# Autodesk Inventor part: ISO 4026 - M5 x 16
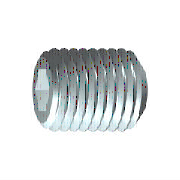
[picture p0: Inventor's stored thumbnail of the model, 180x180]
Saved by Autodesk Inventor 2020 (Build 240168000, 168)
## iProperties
IsCustomPart: 0
Created: 2010-01
Part Number: ISO 4026 - M5 x 16
Material: Stainless Steel, 440C
Description: Hexagon socket set screws with flat point
Document SubType Name: Modeling
Standard: ISO 4026
Designer: sauflet
Standard Revision: Third edition 2003-12-01
Standards Organization: ISO
Language: en-US
Size Designation: M5 x 16
Categories: <MemberInstance><Categories><Category DisplayName="Fasteners" InternalName="e4da775c-781d-43d5-af7c-5136215cf5a6" Mnemonic="FSTN"><Category DisplayName="Bolts"
Density: 7.75 g/cm^3
Appearance: Steel
Author: sauflet
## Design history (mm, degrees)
sketch "Sketch1"
  geometry: L1 (0, 0)-(12.167, 0); L2 (16, 1.443)-(16, 2.5); L3 (16, 2.5)-(0, 2.5); L4 (16, 1.443)-(13, 1.443); L5 (13, 1.443)-(12.167, 0); L6 (0, -0.5)-(0, 3) reference; L7 (0, 2.5)-(0, 0)
  constraints: 13 end point, 3 parallel, 1 collinear, 1 perpendicular, 1 point on line
  dimensions: "d0" = 3 distance of L2.start L4.end (= INTI); "d1" = 60 deg angle of L5 L1; "d2" = 5 diameter of L3 L1 (= NND); "d3" = 2.88675 diameter of L4 L1 (= 1.1547 x SW); "d5" = 16 distance from line of L2 L3.end (= NLG)
revolve "Body" sketch "Sketch1" stored, may be unused: angle "d6" = 90 deg
sketch "Sketch2"
  geometry: L1 (-0.722, 1.25)-(0.722, 1.25); L2 (0.722, 1.25)-(1.443, 0); L3 (1.443, 0)-(0.722, -1.25); L4 (0.722, -1.25)-(-0.722, -1.25); L5 (-0.722, -1.25)-(-1.443, 0); L6 (-1.443, 0)-(-0.722, 1.25); A1 r 1.443 centre (0, 0) between (-0.722, 1.25) and (0.722, 1.25) reference; 2 further points
  constraints: 12 end point, 2 point on circle, 1 coincident, 1 horizontal, 11 other
extrude "Slot" join sketch "Sketch2" taper "d9" = 0 deg; stored distance "d21" = 10
workaxis "Work Axis1"
workplane "Work Plane1"
body "Solid1"
chamfer "Chamfer1" distance "d7" = 0.49076 (= -0.5 x GD1 + 0.5 x NND); stored, may be unused: angle "d8" = 45 deg (= FAWI), second distance "d29" = 0.49076 (= -0.5 x GD1 + 0.5 x NND)
feature "Thread" dims "d11" = 16 (= NLG), "d12" = 0
chamfer "Chamfer2" distance "d13" = 0.49076 (= -0.5 x GD1 + 0.5 x NND); stored, may be unused: angle "d14" = 45 deg (= FAWI), second distance "d30" = 0.49076 (= -0.5 x GD1 + 0.5 x NND)
other parameters: "NND" = 5 [user parameter; used in 5 equation terms], "NLG" = 16 [user parameter; used in 2 equation terms], "INTI" = 3 [user parameter; used in 1 equation term], "FAWI" = 45 deg [user parameter; used in 2 equation terms], "SW" = 2.5 [user parameter; used in 2 equation terms], "GD1" = 4.01848 (= THREADDIA - 1.2269 x PTC) [user parameter; used in 4 equation terms], "d4" = 0, "FAWI1" = 45 deg [user parameter], "d15" = 0, "d31" = 0, "GUL" = 0.49076 (= 0.61345 x PTC) [user parameter], "SPD" = 3.5 [user parameter], "SEWI" = 90 deg [user parameter], "TOA" = 30 deg [user parameter], "THREADDIA" = 5 [user parameter; used in 1 equation term], "TPU" = 12.5 (computed from PTC) [user parameter], "PTC" = 0.8 [user parameter; used in 4 equation terms], "GAL" = 0.49076 (= 0.61345 x PTC) [user parameter], "E0" = 2.8875 (= 1.155 x SW) [user parameter]
